(* Logix 5000 project; controller GracoPd2kDual_Example vendor 1 type 14 code 196 rev 32.11; software revision 32.04; part 4 of 4 *)
(* tags used below, declared in another part *)
   io_statusUDT : GracoPd2kDual_TypePd2kDualStatus;   // Status UDT
(* GracoPd2kDual_StatusToUDT, continued *)

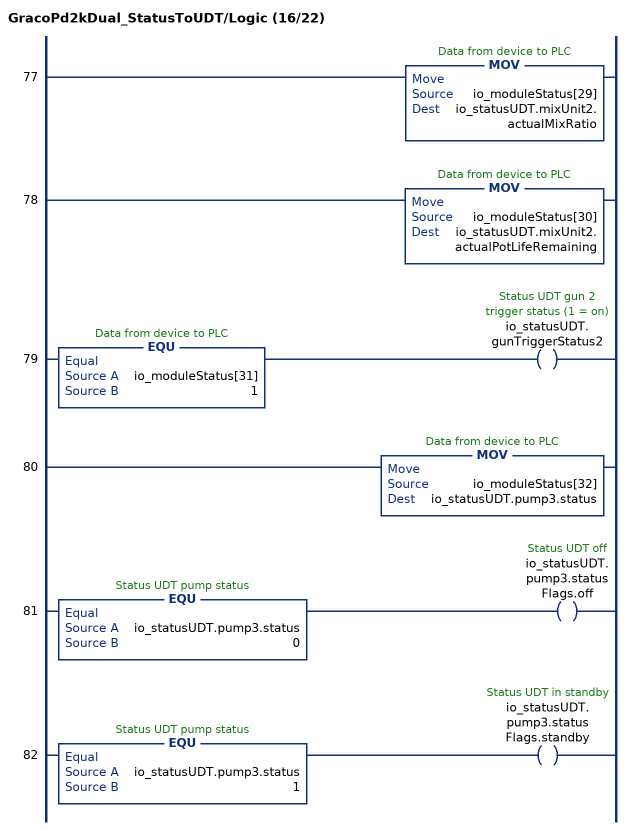
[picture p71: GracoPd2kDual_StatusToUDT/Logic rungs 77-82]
   77: MOV(io_moduleStatus[29],io_statusUDT.mixUnit2.actualMixRatio);
   78: MOV(io_moduleStatus[30],io_statusUDT.mixUnit2.actualPotLifeRemaining);
   79: EQU(io_moduleStatus[31],1)OTE(io_statusUDT.gunTriggerStatus2);
   80: MOV(io_moduleStatus[32],io_statusUDT.pump3.status);
   81: EQU(io_statusUDT.pump3.status,0)OTE(io_statusUDT.pump3.statusFlags.off);
   82: EQU(io_statusUDT.pump3.status,1)OTE(io_statusUDT.pump3.statusFlags.standby);
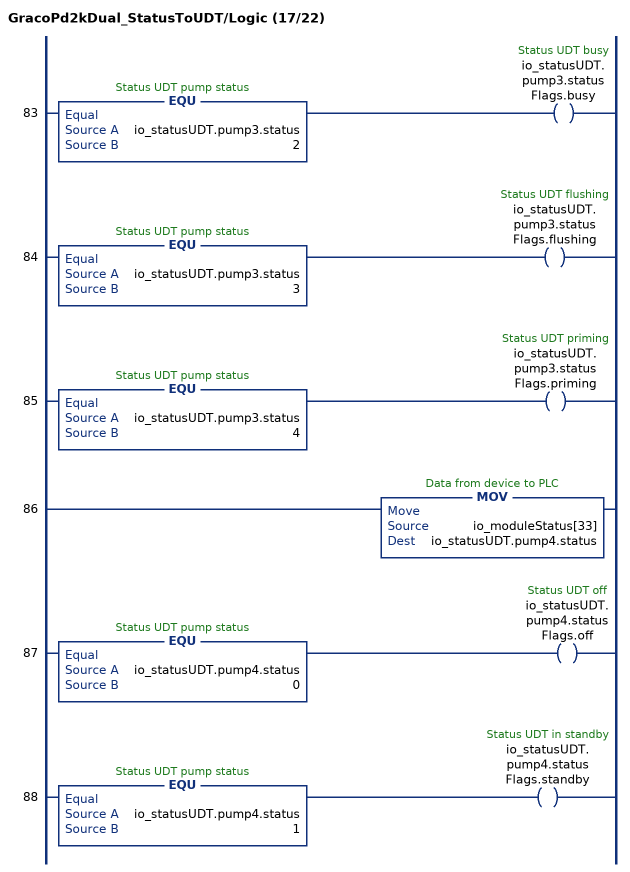
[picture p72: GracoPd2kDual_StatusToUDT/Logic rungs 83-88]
   83: EQU(io_statusUDT.pump3.status,2)OTE(io_statusUDT.pump3.statusFlags.busy);
   84: EQU(io_statusUDT.pump3.status,3)OTE(io_statusUDT.pump3.statusFlags.flushing);
   85: EQU(io_statusUDT.pump3.status,4)OTE(io_statusUDT.pump3.statusFlags.priming);
   86: MOV(io_moduleStatus[33],io_statusUDT.pump4.status);
   87: EQU(io_statusUDT.pump4.status,0)OTE(io_statusUDT.pump4.statusFlags.off);
   88: EQU(io_statusUDT.pump4.status,1)OTE(io_statusUDT.pump4.statusFlags.standby);
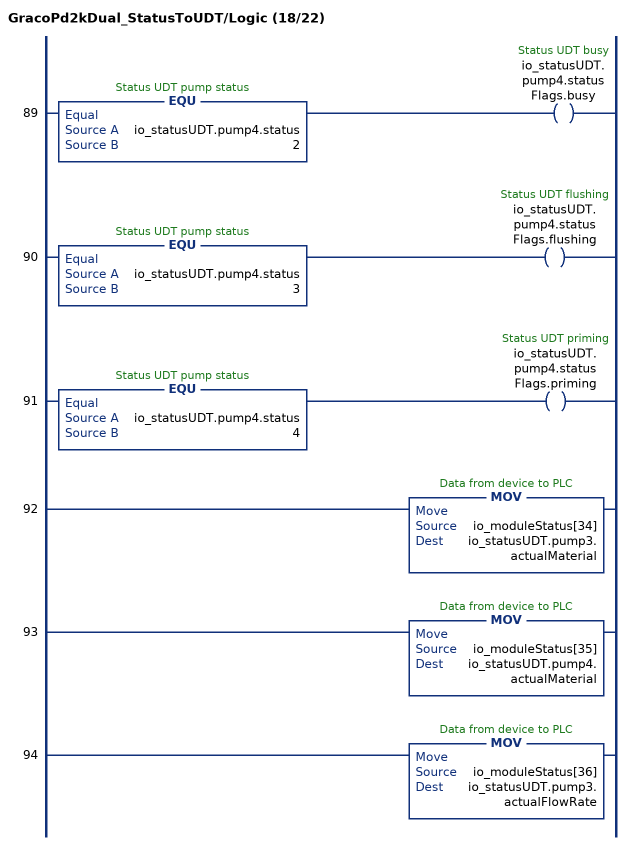
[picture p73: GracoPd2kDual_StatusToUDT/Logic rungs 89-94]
   89: EQU(io_statusUDT.pump4.status,2)OTE(io_statusUDT.pump4.statusFlags.busy);
   90: EQU(io_statusUDT.pump4.status,3)OTE(io_statusUDT.pump4.statusFlags.flushing);
   91: EQU(io_statusUDT.pump4.status,4)OTE(io_statusUDT.pump4.statusFlags.priming);
   92: MOV(io_moduleStatus[34],io_statusUDT.pump3.actualMaterial);
   93: MOV(io_moduleStatus[35],io_statusUDT.pump4.actualMaterial);
   94: MOV(io_moduleStatus[36],io_statusUDT.pump3.actualFlowRate);
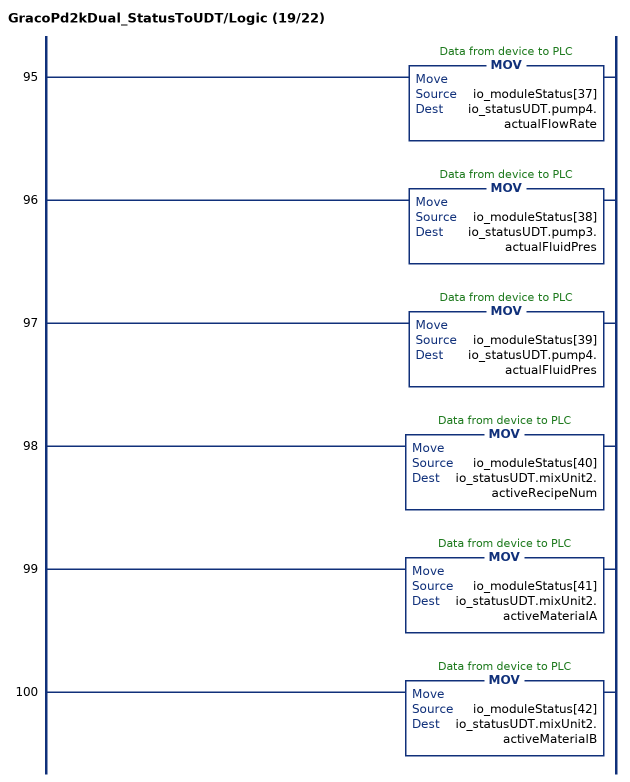
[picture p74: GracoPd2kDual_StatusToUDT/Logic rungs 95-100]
   95: MOV(io_moduleStatus[37],io_statusUDT.pump4.actualFlowRate);
   96: MOV(io_moduleStatus[38],io_statusUDT.pump3.actualFluidPres);
   97: MOV(io_moduleStatus[39],io_statusUDT.pump4.actualFluidPres);
   98: MOV(io_moduleStatus[40],io_statusUDT.mixUnit2.activeRecipeNum);
   99: MOV(io_moduleStatus[41],io_statusUDT.mixUnit2.activeMaterialA);
   100: MOV(io_moduleStatus[42],io_statusUDT.mixUnit2.activeMaterialB);
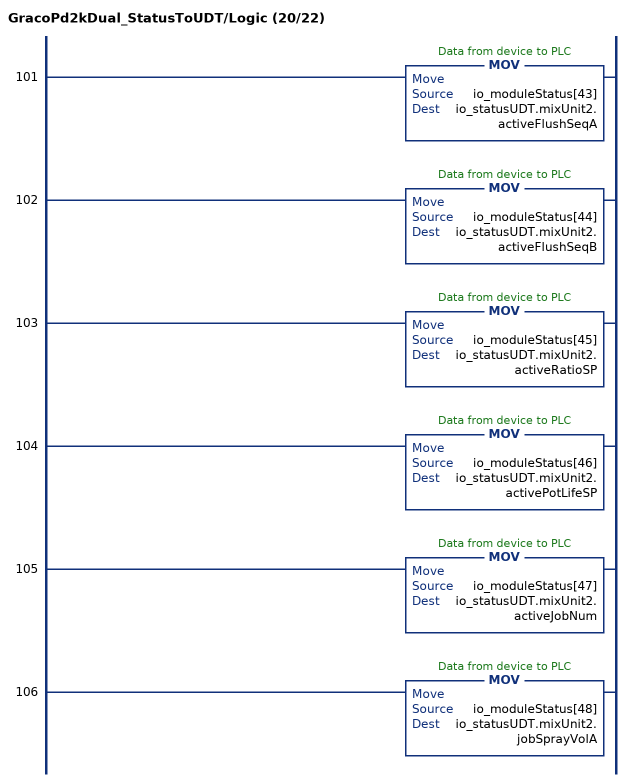
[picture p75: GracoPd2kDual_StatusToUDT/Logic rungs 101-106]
   101: MOV(io_moduleStatus[43],io_statusUDT.mixUnit2.activeFlushSeqA);
   102: MOV(io_moduleStatus[44],io_statusUDT.mixUnit2.activeFlushSeqB);
   103: MOV(io_moduleStatus[45],io_statusUDT.mixUnit2.activeRatioSP);
   104: MOV(io_moduleStatus[46],io_statusUDT.mixUnit2.activePotLifeSP);
   105: MOV(io_moduleStatus[47],io_statusUDT.mixUnit2.activeJobNum);
   106: MOV(io_moduleStatus[48],io_statusUDT.mixUnit2.jobSprayVolA);
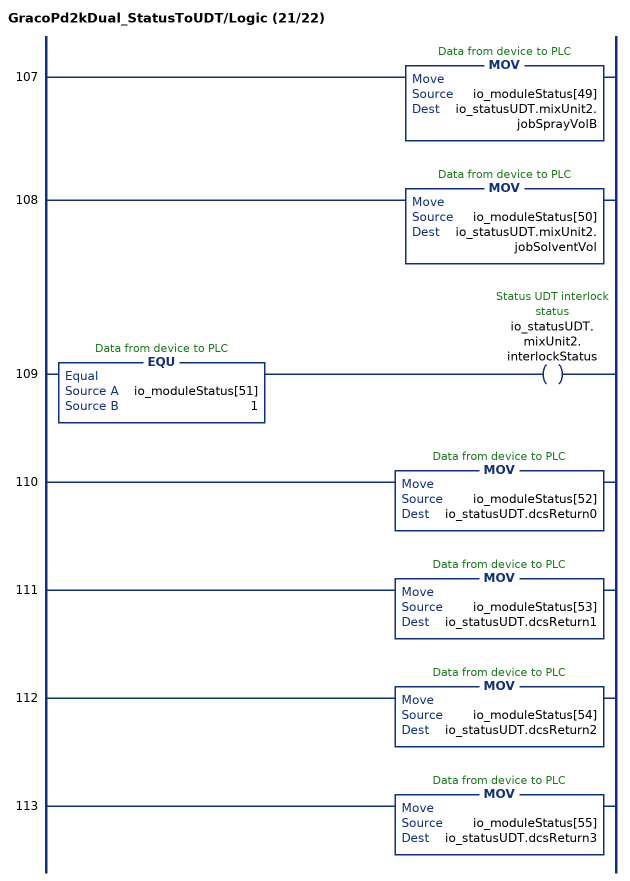
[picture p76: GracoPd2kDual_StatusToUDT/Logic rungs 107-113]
   107: MOV(io_moduleStatus[49],io_statusUDT.mixUnit2.jobSprayVolB);
   108: MOV(io_moduleStatus[50],io_statusUDT.mixUnit2.jobSolventVol);
   109: EQU(io_moduleStatus[51],1)OTE(io_statusUDT.mixUnit2.interlockStatus);
   110: MOV(io_moduleStatus[52],io_statusUDT.dcsReturn0);
   111: MOV(io_moduleStatus[53],io_statusUDT.dcsReturn1);
   112: MOV(io_moduleStatus[54],io_statusUDT.dcsReturn2);
   113: MOV(io_moduleStatus[55],io_statusUDT.dcsReturn3);
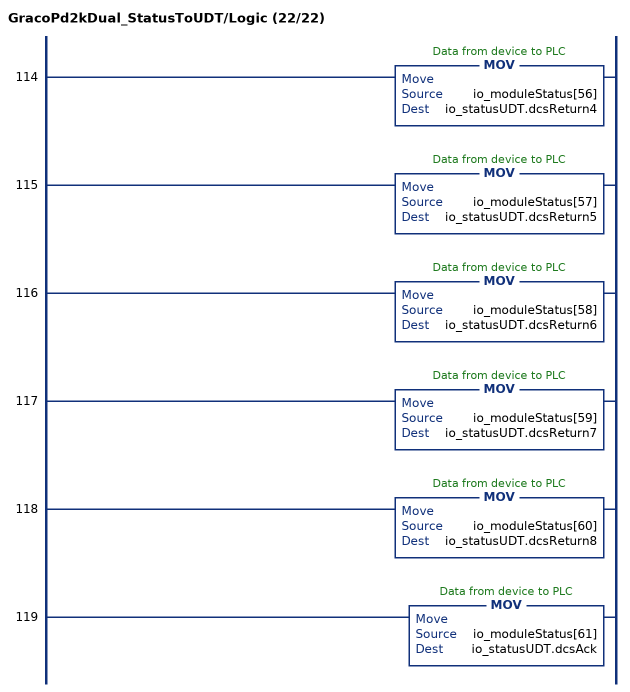
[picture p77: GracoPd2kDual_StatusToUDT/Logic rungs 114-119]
   114: MOV(io_moduleStatus[56],io_statusUDT.dcsReturn4);
   115: MOV(io_moduleStatus[57],io_statusUDT.dcsReturn5);
   116: MOV(io_moduleStatus[58],io_statusUDT.dcsReturn6);
   117: MOV(io_moduleStatus[59],io_statusUDT.dcsReturn7);
   118: MOV(io_moduleStatus[60],io_statusUDT.dcsReturn8);
   119: MOV(io_moduleStatus[61],io_statusUDT.dcsAck);
END_ROUTINE
END_ADD_ON_INSTRUCTION

ADD_ON_INSTRUCTION GracoPd2kDual_WriteFlushSeq   (* revision 1.0 *)
// Help:
// Configures the values for a flush sequence number.
// Values outside of acceptable ranges will result in an error being raised.
// State Codes:
// * 0000 (IDLE) - Idle
// * 1000 (BUSY) - Busy
// * 2000 (DONE) - Done
// * 4000 (ABORT) - Command overwritten by another process
// * 8000 (ERROR) - Flush sequence number out of range
// * 8001 (ERROR) - Timeout waiting for DCS registers
// * 8002 (ERROR) - Command unsuccessful
// * 8003 (ERROR) - Unhandled internal error
VAR_INPUT
   i_execute : BOOL; {visible}   // Execute command
   i_flushSeqNum : DINT; {visible}   // Flush sequence number
   i_gunPurgeTime : DINT; {visible}   // Gun purge time (s)
   i_initialFlushVol : DINT; {visible}   // Initial flush volume (cc)
   i_finalFlushVol : DINT; {visible}   // Final flush volume (cc)
   i_numWashCycles : DINT; {visible}   // Number of wash cycles
   i_strokesPerWashCycle : DINT; {visible}   // Strokes per wash cycle
END_VAR
VAR_OUTPUT
   o_busy : BOOL; {access Read Only, visible}   // Busy flag
   o_done : BOOL; {access Read Only, visible}   // Done flag
   o_aborted : BOOL; {access Read Only, visible}   // Aborted flag
   o_error : BOOL; {access Read Only, visible}   // Error flag
   o_state : DINT; {access Read Only, visible}   // Command state
END_VAR
VAR_IN_OUT
   io_moduleStatus : DINT[62]; {required}   // Data from device to PLC
   io_moduleCmds : DINT[30]; {required}   // Data from PLC to device
END_VAR
VAR
   sendDCSInst : GracoPd2kDual_SendDCS; {access None}   // SendDCS instruction
END_VAR

ROUTINE Logic   (* ladder *)
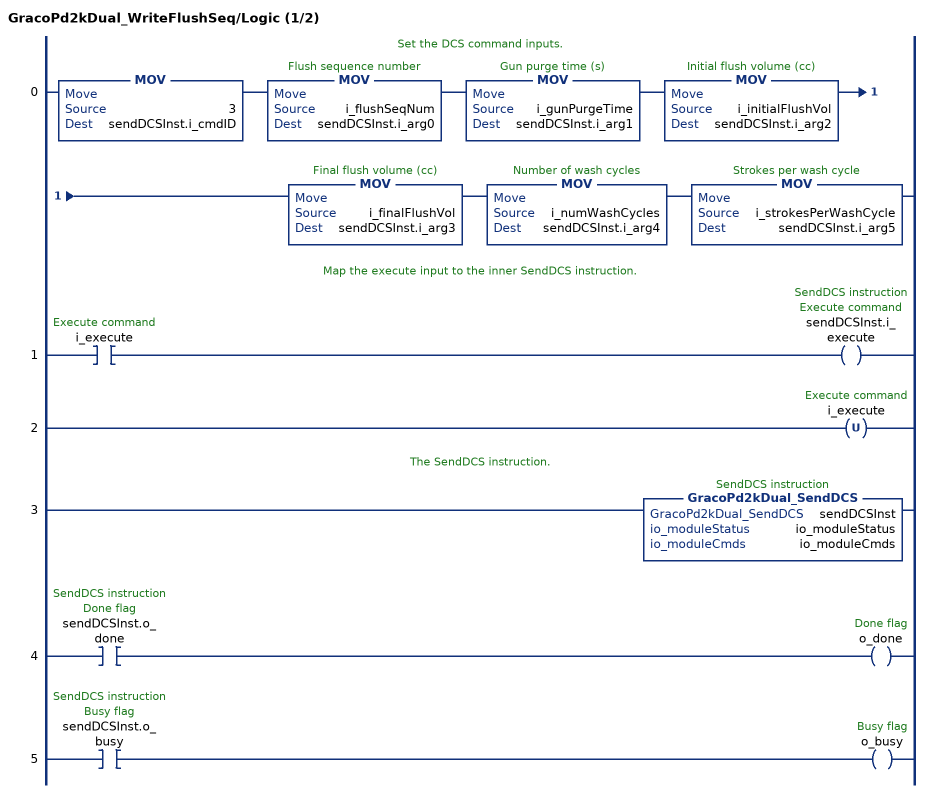
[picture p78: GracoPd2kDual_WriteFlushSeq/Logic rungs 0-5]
   // Set the DCS command inputs.
   0: MOV(3,sendDCSInst.i_cmdID)MOV(i_flushSeqNum,sendDCSInst.i_arg0)MOV(i_gunPurgeTime,sendDCSInst.i_arg1)MOV(i_initialFlushVol,sendDCSInst.i_arg2)MOV(i_finalFlushVol,sendDCSInst.i_arg3)MOV(i_numWashCycles,sendDCSInst.i_arg4)MOV(i_strokesPerWashCycle,sendDCSInst.i_arg5);
   // Map the execute input to the inner SendDCS instruction.
   1: XIC(i_execute)OTE(sendDCSInst.i_execute);
   2: OTU(i_execute);
   // The SendDCS instruction.
   3: GracoPd2kDual_SendDCS(sendDCSInst,io_moduleStatus,io_moduleCmds);
   4: XIC(sendDCSInst.o_done)OTE(o_done);
   5: XIC(sendDCSInst.o_busy)OTE(o_busy);
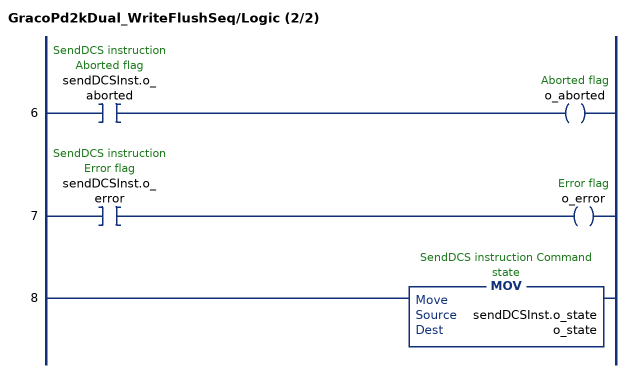
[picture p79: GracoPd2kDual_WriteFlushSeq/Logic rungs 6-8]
   6: XIC(sendDCSInst.o_aborted)OTE(o_aborted);
   7: XIC(sendDCSInst.o_error)OTE(o_error);
   8: MOV(sendDCSInst.o_state,o_state);
END_ROUTINE
END_ADD_ON_INSTRUCTION

ADD_ON_INSTRUCTION GracoPd2kDual_WriteMaterialReadyFlag   (* revision 1.0 *)
// Help:
// Sets the material ready flag, which is used to signal the state of upstream material management to the PD2K.
// This flag is only used when multiple material for a pump are fed to the PD2K via a single valve at the inlet valve stack (i.e. a piggable system). For more information, see the system operation manual.
// State Codes:
// * 0000 (IDLE) - Idle
// * 1000 (BUSY) - Busy
// * 2000 (DONE) - Done
// * 4000 (ABORT) - Command overwritten by another process
// * 8000 (ERROR) - Mix unit number out of range
// * 8001 (ERROR) - Timeout waiting for DCS registers
// * 8002 (ERROR) - Command unsuccessful
// * 8003 (ERROR) - Unhandled internal error
VAR_INPUT
   i_mixUnitNum : DINT; {visible}   // Mix unit number
   i_execute : BOOL; {visible}   // Execute command
   i_materialReadyFlag : BOOL; {visible}   // Material ready flag
END_VAR
VAR_OUTPUT
   o_busy : BOOL; {access Read Only, visible}   // Busy flag
   o_done : BOOL; {access Read Only, visible}   // Done flag
   o_aborted : BOOL; {access Read Only, visible}   // Aborted flag
   o_error : BOOL; {access Read Only, visible}   // Error flag
END_VAR
VAR_IN_OUT
   io_moduleStatus : DINT[62]; {required}   // Data from device to PLC
   io_moduleCmds : DINT[30]; {required}   // Data from PLC to device
END_VAR
VAR_OUTPUT
   o_state : DINT; {access Read Only, visible}   // Command state
END_VAR
VAR
   sendDCSInst : GracoPd2kDual_SendDCS; {access None}   // SendDCS instruction
END_VAR

ROUTINE Logic   (* ladder *)
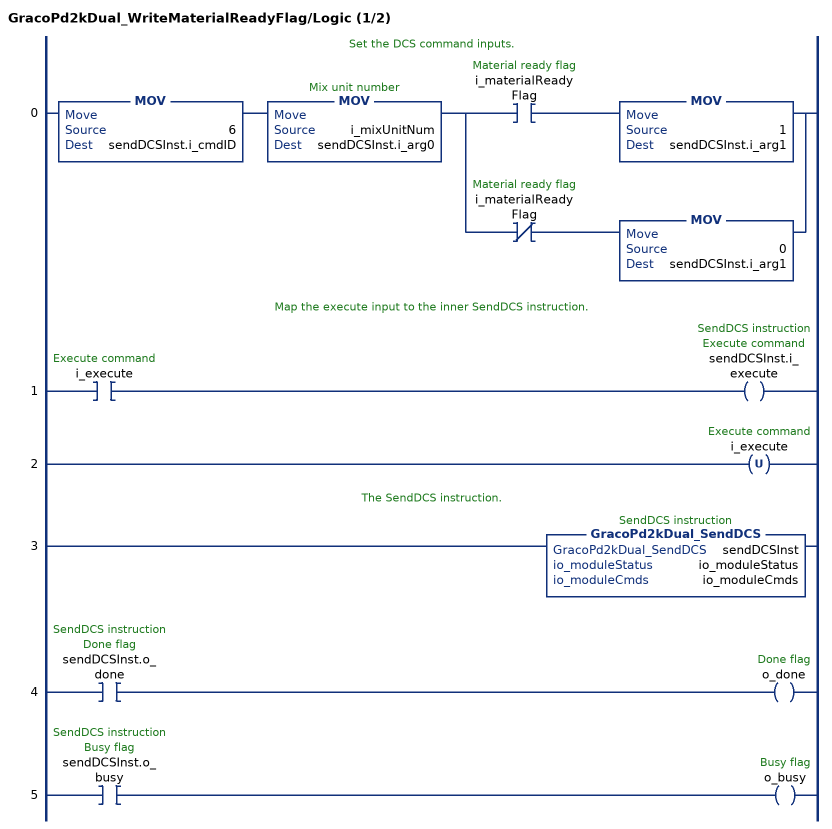
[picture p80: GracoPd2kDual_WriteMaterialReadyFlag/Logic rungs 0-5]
   // Set the DCS command inputs.
   0: MOV(6,sendDCSInst.i_cmdID)MOV(i_mixUnitNum,sendDCSInst.i_arg0)[XIC(i_materialReadyFlag) MOV(1,sendDCSInst.i_arg1) ,XIO(i_materialReadyFlag) MOV(0,sendDCSInst.i_arg1) ];
   // Map the execute input to the inner SendDCS instruction.
   1: XIC(i_execute)OTE(sendDCSInst.i_execute);
   2: OTU(i_execute);
   // The SendDCS instruction.
   3: GracoPd2kDual_SendDCS(sendDCSInst,io_moduleStatus,io_moduleCmds);
   4: XIC(sendDCSInst.o_done)OTE(o_done);
   5: XIC(sendDCSInst.o_busy)OTE(o_busy);
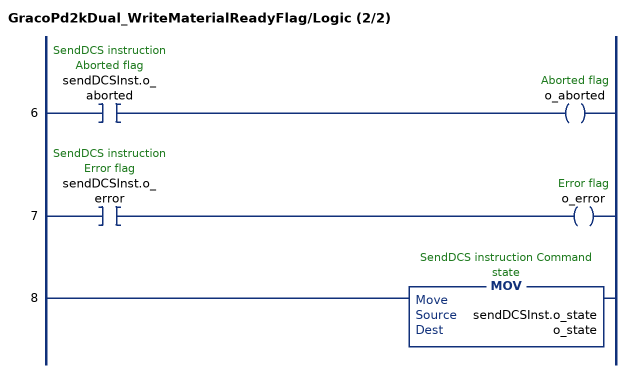
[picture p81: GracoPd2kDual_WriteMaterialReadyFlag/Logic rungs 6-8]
   6: XIC(sendDCSInst.o_aborted)OTE(o_aborted);
   7: XIC(sendDCSInst.o_error)OTE(o_error);
   8: MOV(sendDCSInst.o_state,o_state);
END_ROUTINE
END_ADD_ON_INSTRUCTION

ADD_ON_INSTRUCTION GracoPd2kDual_WriteRecipe   (* revision 1.0 *)
// Help:
// Configures the values for a recipe number.
// Values outside of acceptable ranges will result in an error being raised.
// For mixRatioSP, the value corresponds to the ratio antecedent, i.e. the material A amount. For example, a value of 2.5 corresponds to a ratio of 2.5:1 (material A to material B). For single component recipes, set the value to 0. The max precision is two decimal places; anything beyond that will be rounded off.
// State Codes:
// * 0000 (IDLE) - Idle
// * 1000 (BUSY) - Busy
// * 2000 (DONE) - Done
// * 4000 (ABORT) - Command overwritten by another process
// * 8000 (ERROR) - Invalid input ranges
// * 8001 (ERROR) - Timeout waiting for DCS registers
// * 8002 (ERROR) - Command unsuccessful
// * 8003 (ERROR) - Unhandled internal error
VAR_INPUT
   i_execute : BOOL; {visible}   // Execute command
   i_mixUnitNum : DINT; {visible}   // Mix unit number
   i_recipeNum : DINT; {visible}   // Recipe number
   i_materialA : DINT; {visible}   // Material A
   i_materialB : DINT; {visible}   // Material B
   i_flushSeqA : DINT; {visible}   // Flush sequence A
   i_flushSeqB : DINT; {visible}   // Flush sequence B
   i_mixRatioSP : REAL; {visible}   // Mix ratio setpoint (A:B)
   i_potLifeTimeSP : DINT; {visible}   // Pot life time setpoint (min)
   i_mixPressureTol : DINT; {visible}   // Mix pressure tolerance (%)
END_VAR
VAR_OUTPUT
   o_busy : BOOL; {access Read Only, visible}   // Busy flag
   o_done : BOOL; {access Read Only, visible}   // Done flag
   o_aborted : BOOL; {access Read Only, visible}   // Aborted flag
   o_error : BOOL; {access Read Only, visible}   // Error flag
   o_state : DINT; {access Read Only, visible}   // Command state
END_VAR
VAR_IN_OUT
   io_moduleStatus : DINT[62]; {required}   // Data from device to PLC
   io_moduleCmds : DINT[30]; {required}   // Data from PLC to device
END_VAR
VAR
   sendDCSInst : GracoPd2kDual_SendDCS; {access None}   // SendDCS instruction
END_VAR

ROUTINE Logic   (* ladder *)
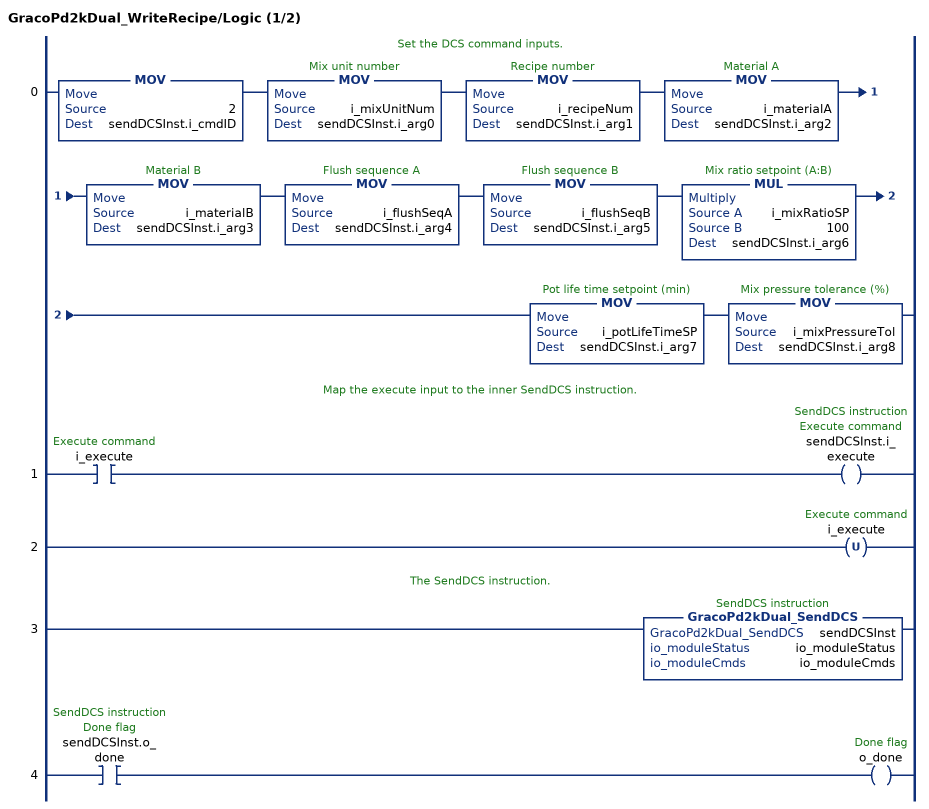
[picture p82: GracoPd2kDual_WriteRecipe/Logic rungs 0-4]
   // Set the DCS command inputs.
   0: MOV(2,sendDCSInst.i_cmdID)MOV(i_mixUnitNum,sendDCSInst.i_arg0)MOV(i_recipeNum,sendDCSInst.i_arg1)MOV(i_materialA,sendDCSInst.i_arg2)MOV(i_materialB,sendDCSInst.i_arg3)MOV(i_flushSeqA,sendDCSInst.i_arg4)MOV(i_flushSeqB,sendDCSInst.i_arg5)MUL(i_mixRatioSP,100,sendDCSInst.i_arg6)MOV(i_potLifeTimeSP,sendDCSInst.i_arg7)MOV(i_mixPressureTol,sendDCSInst.i_arg8);
   // Map the execute input to the inner SendDCS instruction.
   1: XIC(i_execute)OTE(sendDCSInst.i_execute);
   2: OTU(i_execute);
   // The SendDCS instruction.
   3: GracoPd2kDual_SendDCS(sendDCSInst,io_moduleStatus,io_moduleCmds);
   4: XIC(sendDCSInst.o_done)OTE(o_done);
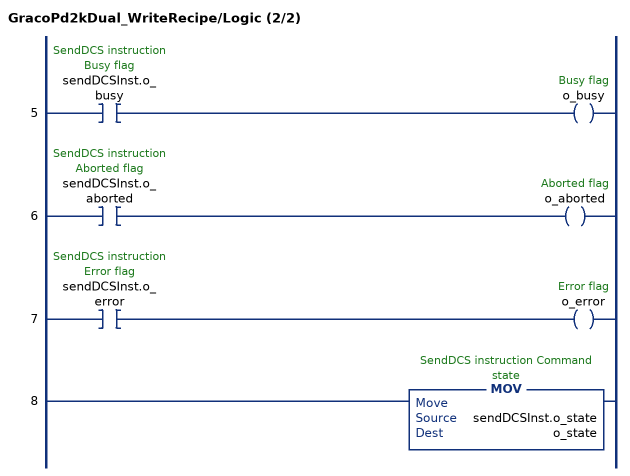
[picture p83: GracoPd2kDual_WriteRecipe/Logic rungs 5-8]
   5: XIC(sendDCSInst.o_busy)OTE(o_busy);
   6: XIC(sendDCSInst.o_aborted)OTE(o_aborted);
   7: XIC(sendDCSInst.o_error)OTE(o_error);
   8: MOV(sendDCSInst.o_state,o_state);
END_ROUTINE
END_ADD_ON_INSTRUCTION

ADD_ON_INSTRUCTION GracoPd2kDual_WriteUserID   (* revision 1.0 *)
// Help:
// Sets the current user ID for the system.
// The user ID can be up to 9 characters in length. The value sent to the PD2K will include a null terminator for a total of 10 characters. Only ASCII characters are supported.
// State Codes:
// * 0000 (IDLE) - Idle
// * 1000 (BUSY) - Busy
// * 2000 (DONE) - Done
// * 4000 (ABORT) - Command overwritten by another process
// * 8000 (ERROR) - Mix unit number out of range
// * 8001 (ERROR) - Timeout waiting for DCS registers
// * 8002 (ERROR) - Command unsuccessful
// * 8003 (ERROR) - Unhandled internal error
VAR_INPUT
   i_execute : BOOL; {visible}   // Execute command
END_VAR
VAR_IN_OUT
   io_userID : STRING9; {required}   // User ID
END_VAR
VAR_OUTPUT
   o_busy : BOOL; {access Read Only, visible}   // Busy flag
   o_done : BOOL; {access Read Only, visible}   // Done flag
   o_aborted : BOOL; {access Read Only, visible}   // Aborted flag
   o_error : BOOL; {access Read Only, visible}   // Error flag
   o_state : DINT; {access Read Only, visible}   // Command state
END_VAR
VAR_IN_OUT
   io_moduleStatus : DINT[62]; {required}   // Data from device to PLC
   io_moduleCmds : DINT[30]; {required}   // Data from PLC to device
END_VAR
VAR_INPUT
   i_mixUnitNum : DINT; {visible}   // Mix unit number
END_VAR
VAR
   sendDCSInst : GracoPd2kDual_SendDCS; {access None}   // SendDCS instruction
   encodeUserID : GracoCore_EncodeUserID; {access None}   // EncodeUserID instruction
END_VAR

ROUTINE Logic   (* ladder *)
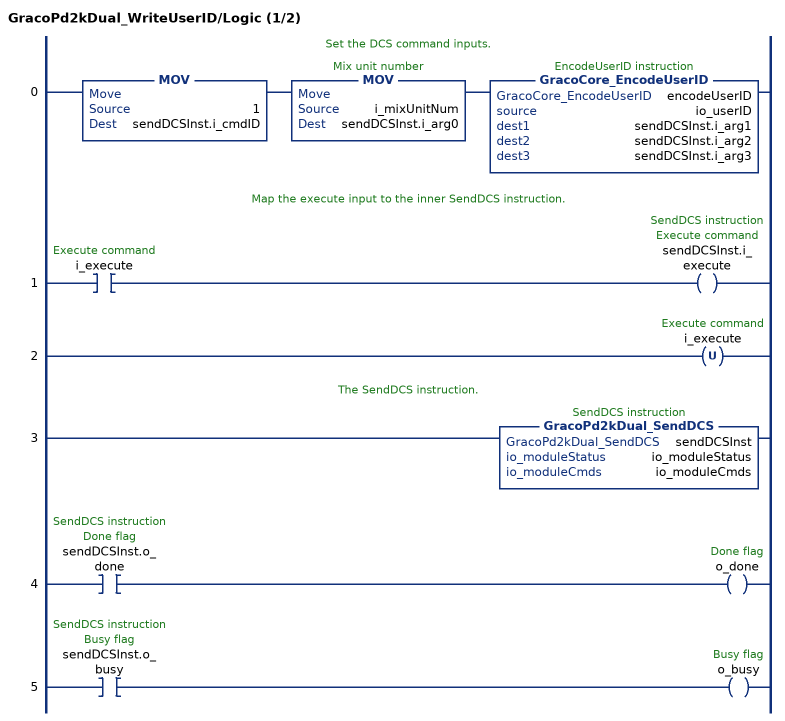
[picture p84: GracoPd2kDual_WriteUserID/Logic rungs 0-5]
   // Set the DCS command inputs.
   0: MOV(1,sendDCSInst.i_cmdID)MOV(i_mixUnitNum,sendDCSInst.i_arg0)GracoCore_EncodeUserID(encodeUserID,io_userID,sendDCSInst.i_arg1,sendDCSInst.i_arg2,sendDCSInst.i_arg3);
   // Map the execute input to the inner SendDCS instruction.
   1: XIC(i_execute)OTE(sendDCSInst.i_execute);
   2: OTU(i_execute);
   // The SendDCS instruction.
   3: GracoPd2kDual_SendDCS(sendDCSInst,io_moduleStatus,io_moduleCmds);
   4: XIC(sendDCSInst.o_done)OTE(o_done);
   5: XIC(sendDCSInst.o_busy)OTE(o_busy);
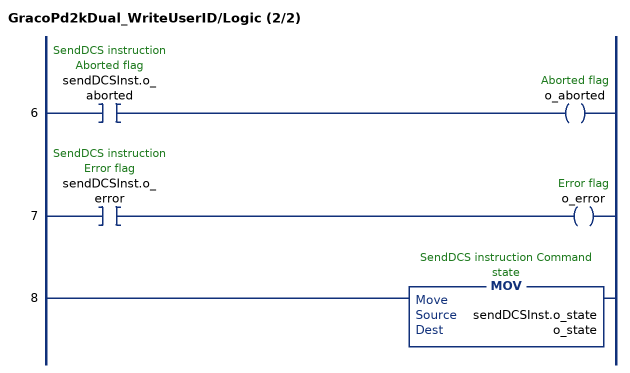
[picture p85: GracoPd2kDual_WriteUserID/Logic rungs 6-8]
   6: XIC(sendDCSInst.o_aborted)OTE(o_aborted);
   7: XIC(sendDCSInst.o_error)OTE(o_error);
   8: MOV(sendDCSInst.o_state,o_state);
END_ROUTINE
END_ADD_ON_INSTRUCTION

VAR_GLOBAL   (* controller tags *)
   GRACO_PD2K_MAIN_CTRL_MU1 : GracoPd2kDual_MainCtrl;   // Graco Example PD2K main control mix unit 1
   GRACO_PD2K_MAIN_CTRL_MU2 : GracoPd2kDual_MainCtrl;
   GRACO_PD2K_RECIPE_CHANGE_MU1 : GracoPd2kDual_RecipeChange;   // Graco Example PD2K recipe change mix unit 1
   GRACO_PD2K_RECIPE_CHANGE_MU2 : GracoPd2kDual_RecipeChange;
   GRACO_PD2K_STATUS : GracoPd2kDual_TypePd2kDualStatus;   // Graco Example PD2K status
   GRACO_PD2K_WRITE_RECIPE_MU1 : GracoPd2kDual_WriteRecipe;
   GRACO_PD2K_WRITE_RECIPE_MU2 : GracoPd2kDual_WriteRecipe;
END_VAR

PROGRAM GRACO_PD2K   (* main routine R00_MainRoutine *)
// Description
VAR
   incRecipeIndexOns : BOOL;
   recipeArraySize : DINT;
   statusToUDT : GracoPd2kDual_StatusToUDT;   // StatusToUDT instruction
   updateRecipeIndex : DINT;
   updateRecipeIndexInit : BOOL;
   updateRecipeSeqDone : BOOL;
   updateRecipeSeqInactive : BOOL;
   updateRecipeSeqInProgress : BOOL;
END_VAR

ROUTINE R00_MainRoutine   (* ladder *)
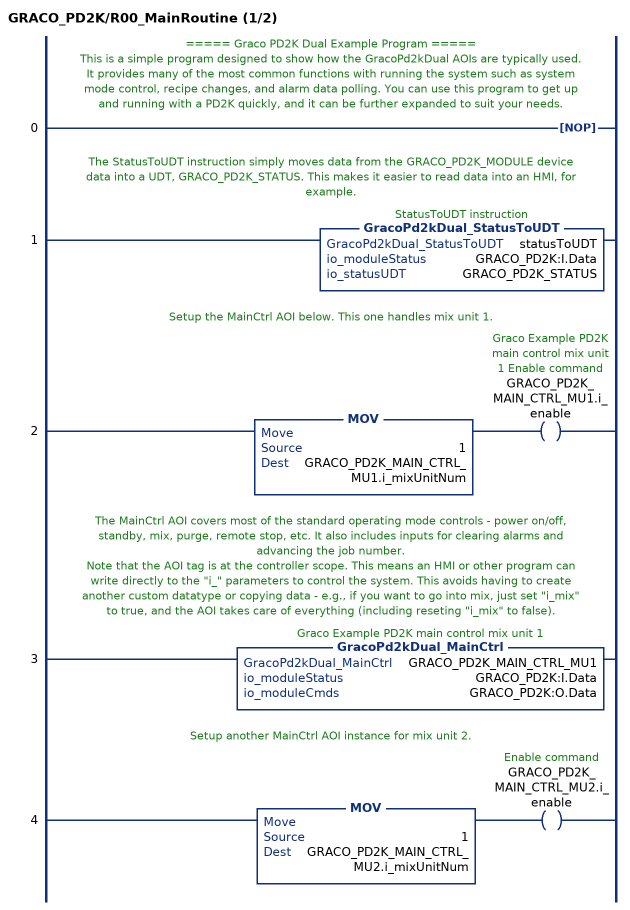
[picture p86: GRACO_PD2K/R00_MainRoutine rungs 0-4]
   // ===== Graco PD2K Dual Example Program =====
   // This is a simple program designed to show how the GracoPd2kDual AOIs are typically used. It provides many of the most common functions with running the system such as system mode control, recipe changes, and alarm data polling. You can use this program to get up and running with a PD2K quickly, and it can be further expanded to suit your needs.
   0: NOP();
   // The StatusToUDT instruction simply moves data from the GRACO_PD2K_MODULE device data into a UDT, GRACO_PD2K_STATUS. This makes it easier to read data into an HMI, for example.
   1: GracoPd2kDual_StatusToUDT(statusToUDT,GRACO_PD2K:I.Data,GRACO_PD2K_STATUS);
   // Setup the MainCtrl AOI below. This one handles mix unit 1.
   2: MOV(1,GRACO_PD2K_MAIN_CTRL_MU1.i_mixUnitNum)OTE(GRACO_PD2K_MAIN_CTRL_MU1.i_enable);
   // The MainCtrl AOI covers most of the standard operating mode controls - power on/off, standby, mix, purge, remote stop, etc. It also includes inputs for clearing alarms and advancing the job number.
   // Note that the AOI tag is at the controller scope. This means an HMI or other program can write directly to the "i_" parameters to control the system. This avoids having to create another custom datatype or copying data - e.g., if you want to go into mix, just set "i_mix" to true, and the AOI takes care of everything (including reseting "i_mix" to false).
   3: GracoPd2kDual_MainCtrl(GRACO_PD2K_MAIN_CTRL_MU1,GRACO_PD2K:I.Data,GRACO_PD2K:O.Data);
   // Setup another MainCtrl AOI instance for mix unit 2.
   4: MOV(1,GRACO_PD2K_MAIN_CTRL_MU2.i_mixUnitNum)OTE(GRACO_PD2K_MAIN_CTRL_MU2.i_enable);
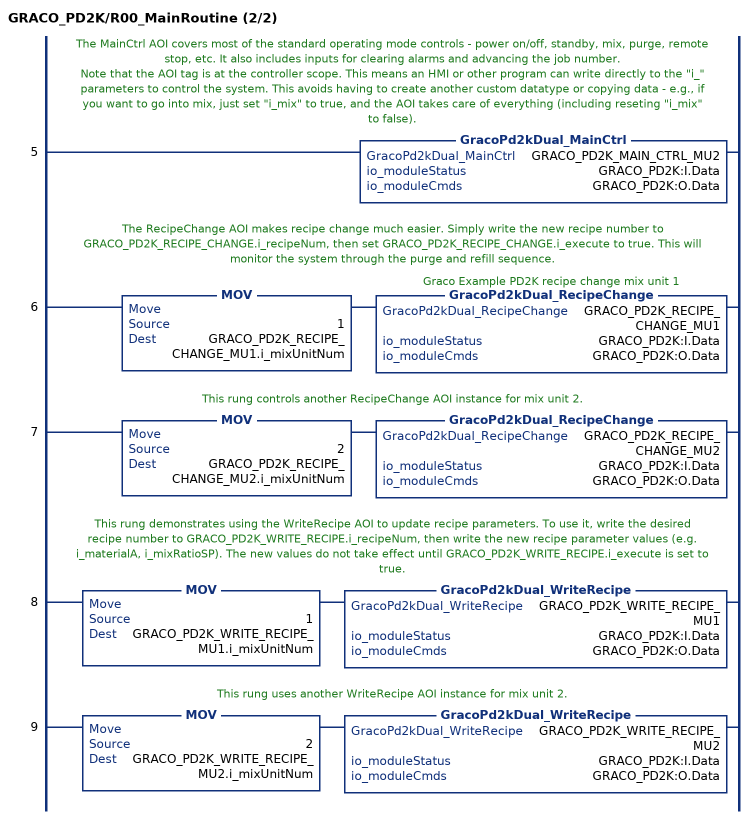
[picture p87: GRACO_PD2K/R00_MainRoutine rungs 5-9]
   // The MainCtrl AOI covers most of the standard operating mode controls - power on/off, standby, mix, purge, remote stop, etc. It also includes inputs for clearing alarms and advancing the job number.
   // Note that the AOI tag is at the controller scope. This means an HMI or other program can write directly to the "i_" parameters to control the system. This avoids having to create another custom datatype or copying data - e.g., if you want to go into mix, just set "i_mix" to true, and the AOI takes care of everything (including reseting "i_mix" to false).
   5: GracoPd2kDual_MainCtrl(GRACO_PD2K_MAIN_CTRL_MU2,GRACO_PD2K:I.Data,GRACO_PD2K:O.Data);
   // The RecipeChange AOI makes recipe change much easier. Simply write the new recipe number to GRACO_PD2K_RECIPE_CHANGE.i_recipeNum, then set GRACO_PD2K_RECIPE_CHANGE.i_execute to true. This will monitor the system through the purge and refill sequence.
   6: MOV(1,GRACO_PD2K_RECIPE_CHANGE_MU1.i_mixUnitNum)GracoPd2kDual_RecipeChange(GRACO_PD2K_RECIPE_CHANGE_MU1,GRACO_PD2K:I.Data,GRACO_PD2K:O.Data);
   // This rung controls another RecipeChange AOI instance for mix unit 2.
   7: MOV(2,GRACO_PD2K_RECIPE_CHANGE_MU2.i_mixUnitNum)GracoPd2kDual_RecipeChange(GRACO_PD2K_RECIPE_CHANGE_MU2,GRACO_PD2K:I.Data,GRACO_PD2K:O.Data);
   // This rung demonstrates using the WriteRecipe AOI to update recipe parameters. To use it, write the desired recipe number to GRACO_PD2K_WRITE_RECIPE.i_recipeNum, then write the new recipe parameter values (e.g. i_materialA, i_mixRatioSP). The new values do not take effect until GRACO_PD2K_WRITE_RECIPE.i_execute is set to true.
   8: MOV(1,GRACO_PD2K_WRITE_RECIPE_MU1.i_mixUnitNum)GracoPd2kDual_WriteRecipe(GRACO_PD2K_WRITE_RECIPE_MU1,GRACO_PD2K:I.Data,GRACO_PD2K:O.Data);
   // This rung uses another WriteRecipe AOI instance for mix unit 2.
   9: MOV(2,GRACO_PD2K_WRITE_RECIPE_MU2.i_mixUnitNum)GracoPd2kDual_WriteRecipe(GRACO_PD2K_WRITE_RECIPE_MU2,GRACO_PD2K:I.Data,GRACO_PD2K:O.Data);
END_ROUTINE
END_PROGRAM
